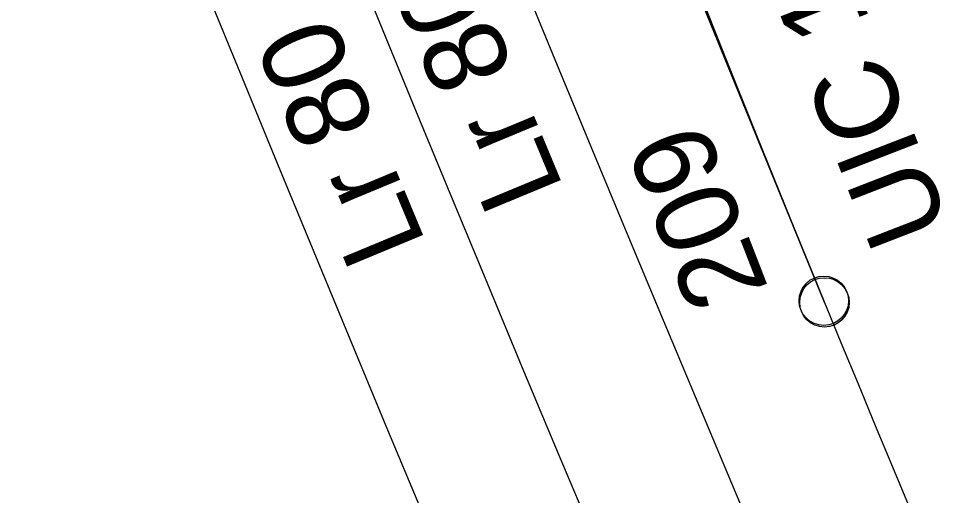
# Model space of a CAD drawing. Extents: x 149855 to 151460, y 6580726 to 6583068.
# Drawn here: x 151020.23 to 151048.78, y 6581433.15 to 6581447.62 of the extents above; entities that cross this region are included whole.
import ezdxf

# ---------------------------------------------------------------- set-up
doc = ezdxf.new("R2010")
doc.units = 0
for name, color, linetype in [('FSK P', 7, 'Continuous'), ('Spårgeometri T', 7, 'Continuous'), ('Spårmitt L', 7, 'Continuous'), ('Tp bef behålls P', 7, 'Continuous'), ('Växel L', 7, 'Continuous'), ('Växelnummer T', 7, 'Continuous'), ('Växeltyp T', 7, 'Continuous')]:
    doc.layers.add(name, color=color, linetype=linetype)

msp = doc.modelspace()

# ---------------------------------------------------------------- linework, layer by layer
at = {"layer": 'FSK P'}
msp.add_circle((151044.69, 6581439.007), 0.75, dxfattribs=at)
at = {"layer": 'Spårmitt L'}
for points in [[(151043.125, 6581430.558), (151042.01, 6581433.189), (151040.901, 6581435.822), (151039.798, 6581438.457), (151038.699, 6581441.095), (151037.606, 6581443.734), (151036.516, 6581446.376), (151035.431, 6581449.019), (151034.35, 6581451.663), (151033.272, 6581454.309), (151032.198, 6581456.957), (151031.126, 6581459.605), (151030.057, 6581462.255), (151028.991, 6581464.906), (151027.926, 6581467.557), (151026.864, 6581470.209), (151025.803, 6581472.862), (151024.743, 6581475.515), (151023.684, 6581478.169), (151022.625, 6581480.823), (151021.567, 6581483.477)], [(151037.777, 6581431.651), (151036.669, 6581434.284), (151035.565, 6581436.92), (151034.467, 6581439.558), (151033.373, 6581442.197), (151032.284, 6581444.838), (151031.199, 6581447.482), (151030.118, 6581450.126), (151029.04, 6581452.772), (151027.966, 6581455.42), (151026.895, 6581458.068), (151025.826, 6581460.718), (151024.759, 6581463.369), (151023.695, 6581466.02), (151022.632, 6581468.672), (151021.571, 6581471.325), (151020.511, 6581473.978), (151019.452, 6581476.632), (151018.394, 6581479.286), (151017.336, 6581481.94)], [(151032.487, 6581432.617), (151031.384, 6581435.253), (151030.286, 6581437.891), (151029.193, 6581440.53), (151028.104, 6581443.172), (151027.019, 6581445.815), (151025.938, 6581448.46), (151024.86, 6581451.106), (151023.786, 6581453.753), (151022.714, 6581456.402), (151021.646, 6581459.052), (151020.579, 6581461.702), (151019.515, 6581464.354), (151018.452, 6581467.006), (151017.391, 6581469.659), (151016.331, 6581472.312), (151015.272, 6581474.966), (151014.214, 6581477.619), (151013.156, 6581480.273)]]:
    msp.add_lwpolyline(points, dxfattribs=at)
for centre, radius, start, end in [((154379.055, 6582805.47), 3603.5, 201.252844, 202.283548), ((151877.457, 6581780.328), 900, 202.283548, 213.397926)]:
    msp.add_arc(centre, radius, start, end, dxfattribs=at)
at = {"layer": 'Tp bef behålls P'}
msp.add_circle((151044.67, 6581439.057), 0.75, dxfattribs=at)
at = {"layer": 'Växel L'}
for p, q in [((151041.178, 6581447.612), (151041.217, 6581447.612)), ((151041.186, 6581447.592), (151041.224, 6581447.592)), ((151041.194, 6581447.572), (151041.232, 6581447.572)), ((151041.202, 6581447.552), (151041.24, 6581447.552)), ((151041.21, 6581447.532), (151041.248, 6581447.532)), ((151041.218, 6581447.512), (151041.256, 6581447.512)), ((151041.226, 6581447.492), (151041.264, 6581447.492)), ((151041.235, 6581447.472), (151041.272, 6581447.472)), ((151041.243, 6581447.452), (151041.28, 6581447.452)), ((151041.251, 6581447.432), (151041.288, 6581447.432)), ((151041.259, 6581447.412), (151041.296, 6581447.412)), ((151041.267, 6581447.392), (151041.304, 6581447.392)), ((151041.275, 6581447.372), (151041.312, 6581447.372)), ((151041.283, 6581447.352), (151041.32, 6581447.352)), ((151041.292, 6581447.332), (151041.328, 6581447.332)), ((151041.3, 6581447.312), (151041.336, 6581447.312)), ((151041.308, 6581447.292), (151041.344, 6581447.292)), ((151041.316, 6581447.272), (151041.352, 6581447.272)), ((151041.324, 6581447.252), (151041.36, 6581447.252)), ((151041.332, 6581447.232), (151041.368, 6581447.232)), ((151041.34, 6581447.212), (151041.376, 6581447.212)), ((151041.349, 6581447.192), (151041.384, 6581447.192)), ((151041.357, 6581447.172), (151041.391, 6581447.172)), ((151041.365, 6581447.152), (151041.399, 6581447.152)), ((151041.373, 6581447.132), (151041.407, 6581447.132)), ((151041.381, 6581447.112), (151041.415, 6581447.112)), ((151041.389, 6581447.092), (151041.423, 6581447.092)), ((151041.397, 6581447.072), (151041.431, 6581447.072)), ((151041.406, 6581447.052), (151041.439, 6581447.052)), ((151041.414, 6581447.032), (151041.447, 6581447.032)), ((151041.422, 6581447.012), (151041.455, 6581447.012)), ((151041.43, 6581446.992), (151041.463, 6581446.992)), ((151041.438, 6581446.972), (151041.471, 6581446.972)), ((151041.446, 6581446.952), (151041.479, 6581446.952)), ((151041.454, 6581446.932), (151041.487, 6581446.932)), ((151041.463, 6581446.912), (151041.495, 6581446.912)), ((151041.471, 6581446.892), (151041.503, 6581446.892)), ((151041.479, 6581446.872), (151041.511, 6581446.872)), ((151041.487, 6581446.852), (151041.519, 6581446.852)), ((151041.495, 6581446.832), (151041.527, 6581446.832)), ((151041.503, 6581446.812), (151041.535, 6581446.812)), ((151041.511, 6581446.792), (151041.543, 6581446.792)), ((151041.52, 6581446.772), (151041.55, 6581446.772)), ((151041.528, 6581446.752), (151041.558, 6581446.752)), ((151041.536, 6581446.732), (151041.566, 6581446.732)), ((151041.544, 6581446.712), (151041.574, 6581446.712)), ((151041.552, 6581446.692), (151041.582, 6581446.692)), ((151041.56, 6581446.672), (151041.59, 6581446.672)), ((151041.568, 6581446.652), (151041.598, 6581446.652)), ((151041.577, 6581446.632), (151041.606, 6581446.632)), ((151041.585, 6581446.612), (151041.614, 6581446.612)), ((151041.593, 6581446.592), (151041.622, 6581446.592)), ((151041.601, 6581446.572), (151041.63, 6581446.572)), ((151041.609, 6581446.552), (151041.638, 6581446.552)), ((151041.617, 6581446.532), (151041.646, 6581446.532)), ((151041.625, 6581446.512), (151041.654, 6581446.512)), ((151041.634, 6581446.492), (151041.662, 6581446.492)), ((151041.642, 6581446.472), (151041.67, 6581446.472)), ((151041.65, 6581446.452), (151041.678, 6581446.452)), ((151041.658, 6581446.432), (151041.686, 6581446.432)), ((151041.666, 6581446.412), (151041.694, 6581446.412)), ((151041.674, 6581446.392), (151041.702, 6581446.392)), ((151041.682, 6581446.372), (151041.71, 6581446.372)), ((151041.691, 6581446.352), (151041.718, 6581446.352)), ((151041.699, 6581446.332), (151041.726, 6581446.332)), ((151041.707, 6581446.312), (151041.734, 6581446.312)), ((151041.715, 6581446.292), (151041.742, 6581446.292)), ((151041.723, 6581446.272), (151041.75, 6581446.272)), ((151041.731, 6581446.252), (151041.758, 6581446.252)), ((151041.739, 6581446.232), (151041.766, 6581446.232)), ((151041.748, 6581446.212), (151041.774, 6581446.212)), ((151041.756, 6581446.192), (151041.782, 6581446.192)), ((151041.764, 6581446.172), (151041.79, 6581446.172)), ((151041.772, 6581446.152), (151041.798, 6581446.152)), ((151041.78, 6581446.132), (151041.806, 6581446.132)), ((151041.788, 6581446.112), (151041.814, 6581446.112)), ((151041.796, 6581446.092), (151041.822, 6581446.092)), ((151041.805, 6581446.072), (151041.83, 6581446.072)), ((151041.813, 6581446.052), (151041.838, 6581446.052)), ((151041.821, 6581446.032), (151041.846, 6581446.032)), ((151041.829, 6581446.012), (151041.854, 6581446.012)), ((151041.837, 6581445.992), (151041.863, 6581445.992)), ((151041.845, 6581445.972), (151041.871, 6581445.972)), ((151041.853, 6581445.952), (151041.879, 6581445.952)), ((151041.862, 6581445.932), (151041.887, 6581445.932)), ((151041.87, 6581445.912), (151041.895, 6581445.912)), ((151041.878, 6581445.892), (151041.903, 6581445.892)), ((151041.886, 6581445.872), (151041.911, 6581445.872)), ((151041.894, 6581445.852), (151041.919, 6581445.852)), ((151041.902, 6581445.832), (151041.927, 6581445.832)), ((151041.91, 6581445.812), (151041.935, 6581445.812)), ((151041.919, 6581445.792), (151041.943, 6581445.792)), ((151041.927, 6581445.772), (151041.951, 6581445.772)), ((151041.935, 6581445.752), (151041.959, 6581445.752)), ((151041.943, 6581445.732), (151041.967, 6581445.732)), ((151041.951, 6581445.712), (151041.975, 6581445.712)), ((151041.959, 6581445.692), (151041.983, 6581445.692)), ((151041.967, 6581445.672), (151041.991, 6581445.672)), ((151041.976, 6581445.652), (151041.999, 6581445.652)), ((151041.984, 6581445.632), (151042.007, 6581445.632)), ((151041.992, 6581445.612), (151042.015, 6581445.612)), ((151042, 6581445.592), (151042.023, 6581445.592)), ((151042.008, 6581445.572), (151042.031, 6581445.572)), ((151042.016, 6581445.552), (151042.039, 6581445.552)), ((151042.024, 6581445.532), (151042.047, 6581445.532)), ((151042.033, 6581445.512), (151042.055, 6581445.512)), ((151042.041, 6581445.492), (151042.063, 6581445.492)), ((151042.049, 6581445.472), (151042.071, 6581445.472)), ((151042.057, 6581445.452), (151042.079, 6581445.452)), ((151042.065, 6581445.432), (151042.087, 6581445.432)), ((151042.073, 6581445.412), (151042.095, 6581445.412)), ((151042.081, 6581445.392), (151042.103, 6581445.392)), ((151042.09, 6581445.372), (151042.111, 6581445.372)), ((151042.098, 6581445.352), (151042.119, 6581445.352)), ((151042.106, 6581445.332), (151042.127, 6581445.332)), ((151042.114, 6581445.312), (151042.135, 6581445.312)), ((151042.122, 6581445.292), (151042.143, 6581445.292)), ((151042.13, 6581445.272), (151042.151, 6581445.272)), ((151042.138, 6581445.252), (151042.159, 6581445.252)), ((151042.147, 6581445.232), (151042.167, 6581445.232)), ((151042.155, 6581445.212), (151042.175, 6581445.212)), ((151042.163, 6581445.192), (151042.183, 6581445.192)), ((151042.171, 6581445.172), (151042.191, 6581445.172)), ((151042.179, 6581445.152), (151042.199, 6581445.152)), ((151042.187, 6581445.132), (151042.207, 6581445.132)), ((151042.195, 6581445.112), (151042.215, 6581445.112)), ((151042.204, 6581445.092), (151042.223, 6581445.092)), ((151042.212, 6581445.072), (151042.231, 6581445.072)), ((151042.22, 6581445.052), (151042.239, 6581445.052)), ((151042.228, 6581445.032), (151042.247, 6581445.032)), ((151042.236, 6581445.012), (151042.256, 6581445.012)), ((151042.244, 6581444.992), (151042.264, 6581444.992)), ((151042.252, 6581444.972), (151042.272, 6581444.972)), ((151042.261, 6581444.952), (151042.28, 6581444.952)), ((151042.269, 6581444.932), (151042.288, 6581444.932)), ((151042.277, 6581444.912), (151042.296, 6581444.912)), ((151042.285, 6581444.892), (151042.304, 6581444.892)), ((151042.293, 6581444.872), (151042.312, 6581444.872)), ((151042.301, 6581444.852), (151042.32, 6581444.852)), ((151042.31, 6581444.832), (151042.328, 6581444.832)), ((151042.318, 6581444.812), (151042.336, 6581444.812)), ((151042.326, 6581444.792), (151042.344, 6581444.792)), ((151042.334, 6581444.772), (151042.352, 6581444.772)), ((151042.342, 6581444.752), (151042.36, 6581444.752)), ((151042.35, 6581444.732), (151042.368, 6581444.732)), ((151042.358, 6581444.712), (151042.376, 6581444.712)), ((151042.367, 6581444.692), (151042.384, 6581444.692)), ((151042.375, 6581444.672), (151042.392, 6581444.672)), ((151042.383, 6581444.652), (151042.4, 6581444.652)), ((151042.391, 6581444.632), (151042.408, 6581444.632)), ((151042.399, 6581444.612), (151042.416, 6581444.612)), ((151042.407, 6581444.592), (151042.424, 6581444.592)), ((151042.415, 6581444.572), (151042.432, 6581444.572)), ((151042.424, 6581444.552), (151042.44, 6581444.552)), ((151042.432, 6581444.532), (151042.448, 6581444.532)), ((151042.44, 6581444.512), (151042.456, 6581444.512)), ((151042.448, 6581444.492), (151042.464, 6581444.492)), ((151042.456, 6581444.472), (151042.472, 6581444.472)), ((151042.464, 6581444.452), (151042.48, 6581444.452)), ((151042.472, 6581444.432), (151042.488, 6581444.432)), ((151042.481, 6581444.412), (151042.496, 6581444.412)), ((151042.489, 6581444.392), (151042.504, 6581444.392)), ((151042.497, 6581444.372), (151042.512, 6581444.372)), ((151042.505, 6581444.352), (151042.52, 6581444.352)), ((151042.513, 6581444.332), (151042.528, 6581444.332)), ((151042.521, 6581444.312), (151042.536, 6581444.312)), ((151042.529, 6581444.292), (151042.544, 6581444.292)), ((151042.538, 6581444.272), (151042.552, 6581444.272)), ((151042.546, 6581444.252), (151042.56, 6581444.252)), ((151042.554, 6581444.232), (151042.568, 6581444.232)), ((151042.562, 6581444.212), (151042.576, 6581444.212)), ((151042.57, 6581444.192), (151042.584, 6581444.192)), ((151042.578, 6581444.172), (151042.592, 6581444.172)), ((151042.586, 6581444.152), (151042.6, 6581444.152)), ((151042.595, 6581444.132), (151042.608, 6581444.132)), ((151042.603, 6581444.112), (151042.616, 6581444.112)), ((151042.611, 6581444.092), (151042.624, 6581444.092)), ((151042.619, 6581444.072), (151042.632, 6581444.072)), ((151042.627, 6581444.052), (151042.64, 6581444.052)), ((151042.635, 6581444.032), (151042.649, 6581444.032)), ((151042.643, 6581444.012), (151042.657, 6581444.012)), ((151042.652, 6581443.992), (151042.665, 6581443.992)), ((151042.66, 6581443.972), (151042.673, 6581443.972)), ((151042.668, 6581443.952), (151042.681, 6581443.952)), ((151042.676, 6581443.932), (151042.689, 6581443.932)), ((151042.684, 6581443.912), (151042.697, 6581443.912)), ((151042.693, 6581443.892), (151042.705, 6581443.892)), ((151042.701, 6581443.872), (151042.713, 6581443.872)), ((151042.709, 6581443.852), (151042.721, 6581443.852)), ((151042.717, 6581443.832), (151042.729, 6581443.832)), ((151042.725, 6581443.812), (151042.738, 6581443.812)), ((151042.733, 6581443.792), (151042.746, 6581443.792)), ((151042.742, 6581443.772), (151042.754, 6581443.772)), ((151042.75, 6581443.752), (151042.762, 6581443.752)), ((151042.758, 6581443.732), (151042.77, 6581443.732)), ((151042.766, 6581443.712), (151042.778, 6581443.712)), ((151042.774, 6581443.692), (151042.786, 6581443.692)), ((151042.782, 6581443.672), (151042.794, 6581443.672)), ((151042.791, 6581443.652), (151042.802, 6581443.652)), ((151042.799, 6581443.632), (151042.81, 6581443.632)), ((151042.807, 6581443.612), (151042.818, 6581443.612)), ((151042.815, 6581443.592), (151042.827, 6581443.592)), ((151042.823, 6581443.572), (151042.835, 6581443.572)), ((151042.832, 6581443.552), (151042.843, 6581443.552)), ((151042.84, 6581443.532), (151042.851, 6581443.532)), ((151042.848, 6581443.512), (151042.859, 6581443.512)), ((151042.856, 6581443.492), (151042.867, 6581443.492)), ((151042.864, 6581443.472), (151042.875, 6581443.472)), ((151042.872, 6581443.452), (151042.883, 6581443.452)), ((151042.881, 6581443.432), (151042.891, 6581443.432)), ((151042.889, 6581443.412), (151042.899, 6581443.412)), ((151042.897, 6581443.392), (151042.907, 6581443.392)), ((151042.905, 6581443.372), (151042.916, 6581443.372)), ((151042.913, 6581443.352), (151042.924, 6581443.352)), ((151042.922, 6581443.332), (151042.932, 6581443.332)), ((151042.93, 6581443.312), (151042.94, 6581443.312)), ((151042.938, 6581443.292), (151042.948, 6581443.292)), ((151042.946, 6581443.272), (151042.956, 6581443.272)), ((151042.954, 6581443.252), (151042.964, 6581443.252)), ((151042.962, 6581443.232), (151042.972, 6581443.232)), ((151042.971, 6581443.212), (151042.98, 6581443.212)), ((151042.979, 6581443.192), (151042.988, 6581443.192)), ((151042.987, 6581443.172), (151042.996, 6581443.172)), ((151042.995, 6581443.152), (151043.005, 6581443.152)), ((151043.003, 6581443.132), (151043.013, 6581443.132)), ((151043.011, 6581443.112), (151043.021, 6581443.112)), ((151043.02, 6581443.092), (151043.029, 6581443.092)), ((151043.028, 6581443.072), (151043.037, 6581443.072)), ((151043.036, 6581443.052), (151043.045, 6581443.052)), ((151043.044, 6581443.032), (151043.053, 6581443.032)), ((151043.052, 6581443.012), (151043.061, 6581443.012)), ((151043.061, 6581442.992), (151043.069, 6581442.992)), ((151043.069, 6581442.972), (151043.077, 6581442.972)), ((151043.077, 6581442.952), (151043.085, 6581442.952)), ((151043.085, 6581442.932), (151043.094, 6581442.932)), ((151043.093, 6581442.912), (151043.102, 6581442.912)), ((151043.101, 6581442.892), (151043.11, 6581442.892)), ((151043.11, 6581442.872), (151043.118, 6581442.872)), ((151043.118, 6581442.852), (151043.126, 6581442.852)), ((151043.126, 6581442.832), (151043.134, 6581442.832)), ((151043.134, 6581442.812), (151043.142, 6581442.812)), ((151043.142, 6581442.792), (151043.15, 6581442.792)), ((151043.151, 6581442.772), (151043.158, 6581442.772)), ((151043.159, 6581442.752), (151043.166, 6581442.752)), ((151043.167, 6581442.732), (151043.174, 6581442.732)), ((151043.175, 6581442.712), (151043.183, 6581442.712)), ((151043.183, 6581442.692), (151043.191, 6581442.692)), ((151043.191, 6581442.672), (151043.199, 6581442.672)), ((151043.2, 6581442.652), (151043.207, 6581442.652)), ((151043.208, 6581442.632), (151043.215, 6581442.632)), ((151043.216, 6581442.612), (151043.223, 6581442.612)), ((151043.224, 6581442.592), (151043.231, 6581442.592)), ((151043.232, 6581442.572), (151043.239, 6581442.572)), ((151043.24, 6581442.552), (151043.247, 6581442.552)), ((151043.249, 6581442.532), (151043.255, 6581442.532)), ((151043.257, 6581442.512), (151043.263, 6581442.512)), ((151043.265, 6581442.492), (151043.271, 6581442.492)), ((151043.273, 6581442.472), (151043.28, 6581442.472)), ((151043.281, 6581442.452), (151043.288, 6581442.452)), ((151043.29, 6581442.432), (151043.296, 6581442.432)), ((151043.298, 6581442.412), (151043.304, 6581442.412)), ((151043.306, 6581442.392), (151043.312, 6581442.392)), ((151043.314, 6581442.372), (151043.32, 6581442.372)), ((151043.322, 6581442.352), (151043.328, 6581442.352)), ((151043.33, 6581442.332), (151043.336, 6581442.332)), ((151043.339, 6581442.312), (151043.344, 6581442.312)), ((151043.347, 6581442.292), (151043.352, 6581442.292)), ((151043.355, 6581442.272), (151043.36, 6581442.272)), ((151043.363, 6581442.252), (151043.369, 6581442.252)), ((151043.371, 6581442.232), (151043.377, 6581442.232)), ((151043.38, 6581442.212), (151043.385, 6581442.212)), ((151043.388, 6581442.192), (151043.393, 6581442.192)), ((151043.396, 6581442.172), (151043.401, 6581442.172)), ((151043.404, 6581442.152), (151043.409, 6581442.152)), ((151043.412, 6581442.132), (151043.417, 6581442.132)), ((151043.42, 6581442.112), (151043.425, 6581442.112)), ((151043.429, 6581442.092), (151043.433, 6581442.092)), ((151043.437, 6581442.072), (151043.441, 6581442.072)), ((151043.445, 6581442.052), (151043.449, 6581442.052)), ((151043.453, 6581442.032), (151043.458, 6581442.032)), ((151043.461, 6581442.012), (151043.466, 6581442.012)), ((151043.469, 6581441.992), (151043.474, 6581441.992)), ((151043.478, 6581441.972), (151043.482, 6581441.972)), ((151043.486, 6581441.952), (151043.49, 6581441.952)), ((151043.494, 6581441.932), (151043.498, 6581441.932)), ((151043.502, 6581441.912), (151043.506, 6581441.912)), ((151043.51, 6581441.892), (151043.514, 6581441.892)), ((151043.519, 6581441.872), (151043.522, 6581441.872)), ((151043.527, 6581441.852), (151043.53, 6581441.852)), ((151043.535, 6581441.832), (151043.538, 6581441.832)), ((151043.543, 6581441.812), (151043.547, 6581441.812)), ((151043.551, 6581441.792), (151043.555, 6581441.792)), ((151043.559, 6581441.772), (151043.563, 6581441.772)), ((151043.568, 6581441.752), (151043.571, 6581441.752)), ((151043.576, 6581441.732), (151043.579, 6581441.732)), ((151043.584, 6581441.712), (151043.587, 6581441.712)), ((151043.592, 6581441.692), (151043.595, 6581441.692)), ((151043.6, 6581441.672), (151043.603, 6581441.672)), ((151043.609, 6581441.652), (151043.611, 6581441.652)), ((151043.617, 6581441.632), (151043.619, 6581441.632)), ((151043.625, 6581441.612), (151043.627, 6581441.612)), ((151043.633, 6581441.592), (151043.636, 6581441.592)), ((151043.641, 6581441.572), (151043.644, 6581441.572)), ((151043.649, 6581441.552), (151043.652, 6581441.552)), ((151043.658, 6581441.532), (151043.66, 6581441.532)), ((151043.666, 6581441.512), (151043.668, 6581441.512)), ((151043.674, 6581441.492), (151043.676, 6581441.492)), ((151043.682, 6581441.472), (151043.684, 6581441.472)), ((151043.69, 6581441.452), (151043.693, 6581441.452)), ((151043.698, 6581441.432), (151043.701, 6581441.432)), ((151043.707, 6581441.412), (151043.709, 6581441.412)), ((151043.715, 6581441.392), (151043.717, 6581441.392)), ((151043.723, 6581441.372), (151043.725, 6581441.372)), ((151043.731, 6581441.352), (151043.733, 6581441.352)), ((151043.739, 6581441.332), (151043.741, 6581441.332)), ((151043.748, 6581441.312), (151043.75, 6581441.312)), ((151043.756, 6581441.292), (151043.758, 6581441.292)), ((151043.764, 6581441.272), (151043.766, 6581441.272)), ((151043.772, 6581441.252), (151043.774, 6581441.252)), ((151043.78, 6581441.232), (151043.782, 6581441.232)), ((151043.788, 6581441.212), (151043.79, 6581441.212)), ((151043.797, 6581441.192), (151043.799, 6581441.192)), ((151043.805, 6581441.172), (151043.807, 6581441.172)), ((151043.813, 6581441.152), (151043.815, 6581441.152)), ((151043.821, 6581441.132), (151043.823, 6581441.132)), ((151043.829, 6581441.112), (151043.831, 6581441.112)), ((151043.838, 6581441.092), (151043.839, 6581441.092)), ((151043.846, 6581441.072), (151043.848, 6581441.072)), ((151043.854, 6581441.052), (151043.856, 6581441.052)), ((151043.862, 6581441.032), (151043.864, 6581441.032)), ((151043.87, 6581441.012), (151043.872, 6581441.012)), ((151043.878, 6581440.992), (151043.88, 6581440.992)), ((151043.887, 6581440.972), (151043.888, 6581440.972)), ((151043.895, 6581440.952), (151043.897, 6581440.952)), ((151043.903, 6581440.932), (151043.905, 6581440.932)), ((151043.911, 6581440.912), (151043.913, 6581440.912)), ((151043.919, 6581440.892), (151043.921, 6581440.892)), ((151043.927, 6581440.872), (151043.929, 6581440.872)), ((151043.936, 6581440.852), (151043.937, 6581440.852)), ((151043.944, 6581440.832), (151043.945, 6581440.832)), ((151043.952, 6581440.812), (151043.954, 6581440.812)), ((151043.96, 6581440.792), (151043.962, 6581440.792)), ((151043.968, 6581440.772), (151043.97, 6581440.772)), ((151043.977, 6581440.752), (151043.978, 6581440.752)), ((151043.985, 6581440.732), (151043.986, 6581440.732)), ((151043.993, 6581440.712), (151043.994, 6581440.712)), ((151044.001, 6581440.692), (151044.003, 6581440.692)), ((151044.009, 6581440.672), (151044.011, 6581440.672)), ((151044.017, 6581440.652), (151044.019, 6581440.652)), ((151044.026, 6581440.632), (151044.027, 6581440.632)), ((151044.034, 6581440.612), (151044.035, 6581440.612)), ((151044.042, 6581440.592), (151044.043, 6581440.592)), ((151044.05, 6581440.572), (151044.052, 6581440.572)), ((151044.058, 6581440.552), (151044.06, 6581440.552)), ((151044.066, 6581440.532), (151044.068, 6581440.532)), ((151044.075, 6581440.512), (151044.076, 6581440.512)), ((151044.083, 6581440.492), (151044.084, 6581440.492)), ((151044.091, 6581440.472), (151044.092, 6581440.472)), ((151044.099, 6581440.452), (151044.101, 6581440.452)), ((151044.107, 6581440.432), (151044.109, 6581440.432)), ((151044.116, 6581440.412), (151044.117, 6581440.412)), ((151044.124, 6581440.392), (151044.125, 6581440.392)), ((151044.132, 6581440.372), (151044.133, 6581440.372)), ((151044.14, 6581440.352), (151044.141, 6581440.352)), ((151044.148, 6581440.332), (151044.149, 6581440.332)), ((151044.156, 6581440.312), (151044.158, 6581440.312)), ((151044.165, 6581440.292), (151044.166, 6581440.292)), ((151044.173, 6581440.272), (151044.174, 6581440.272)), ((151044.181, 6581440.252), (151044.182, 6581440.252)), ((151044.189, 6581440.232), (151044.19, 6581440.232)), ((151044.197, 6581440.212), (151044.198, 6581440.212)), ((151044.206, 6581440.192), (151044.207, 6581440.192)), ((151044.214, 6581440.172), (151044.215, 6581440.172)), ((151044.222, 6581440.152), (151044.223, 6581440.152)), ((151044.23, 6581440.132), (151044.231, 6581440.132)), ((151044.238, 6581440.112), (151044.239, 6581440.112)), ((151044.246, 6581440.092), (151044.247, 6581440.092)), ((151044.255, 6581440.072), (151044.256, 6581440.072)), ((151044.263, 6581440.052), (151044.264, 6581440.052)), ((151044.271, 6581440.032), (151044.272, 6581440.032)), ((151044.279, 6581440.012), (151044.28, 6581440.012)), ((151044.287, 6581439.992), (151044.288, 6581439.992)), ((151044.295, 6581439.972), (151044.296, 6581439.972)), ((151044.304, 6581439.952), (151044.305, 6581439.952)), ((151044.312, 6581439.932), (151044.313, 6581439.932)), ((151044.32, 6581439.912), (151044.321, 6581439.912)), ((151044.328, 6581439.892), (151044.329, 6581439.892)), ((151044.336, 6581439.872), (151044.337, 6581439.872)), ((151044.345, 6581439.852), (151044.345, 6581439.852)), ((151044.353, 6581439.832), (151044.353, 6581439.832)), ((151044.361, 6581439.812), (151044.362, 6581439.812)), ((151044.369, 6581439.792), (151044.37, 6581439.792)), ((151044.377, 6581439.772), (151044.378, 6581439.772)), ((151044.385, 6581439.752), (151044.386, 6581439.752)), ((151044.394, 6581439.732), (151044.394, 6581439.732)), ((151044.402, 6581439.712), (151044.402, 6581439.712)), ((151044.41, 6581439.692), (151044.411, 6581439.692)), ((151044.418, 6581439.672), (151044.419, 6581439.672)), ((151044.426, 6581439.652), (151044.427, 6581439.652)), ((151044.435, 6581439.632), (151044.435, 6581439.632)), ((151044.443, 6581439.612), (151044.443, 6581439.612)), ((151044.451, 6581439.592), (151044.451, 6581439.592)), ((151044.459, 6581439.572), (151044.46, 6581439.572)), ((151044.467, 6581439.552), (151044.468, 6581439.552)), ((151044.475, 6581439.532), (151044.476, 6581439.532)), ((151044.484, 6581439.512), (151044.484, 6581439.512)), ((151044.492, 6581439.492), (151044.492, 6581439.492)), ((151044.5, 6581439.472), (151044.5, 6581439.472)), ((151044.508, 6581439.452), (151044.509, 6581439.452)), ((151044.516, 6581439.432), (151044.517, 6581439.432)), ((151044.524, 6581439.412), (151044.525, 6581439.412)), ((151044.533, 6581439.392), (151044.533, 6581439.392)), ((151044.541, 6581439.372), (151044.541, 6581439.372)), ((151044.549, 6581439.352), (151044.549, 6581439.352)), ((151044.557, 6581439.332), (151044.557, 6581439.332)), ((151044.565, 6581439.312), (151044.566, 6581439.312)), ((151044.574, 6581439.292), (151044.574, 6581439.292)), ((151044.582, 6581439.272), (151044.582, 6581439.272)), ((151044.59, 6581439.252), (151044.59, 6581439.252)), ((151044.598, 6581439.232), (151044.598, 6581439.232)), ((151044.606, 6581439.212), (151044.606, 6581439.212)), ((151044.614, 6581439.192), (151044.615, 6581439.192)), ((151044.623, 6581439.172), (151044.623, 6581439.172)), ((151044.631, 6581439.152), (151044.631, 6581439.152)), ((151044.639, 6581439.132), (151044.639, 6581439.132)), ((151044.647, 6581439.112), (151044.647, 6581439.112)), ((151044.655, 6581439.092), (151044.655, 6581439.092)), ((151044.664, 6581439.072), (151044.664, 6581439.072)), ((151044.672, 6581439.052), (151044.672, 6581439.052)), ((151044.68, 6581439.032), (151044.68, 6581439.032)), ((151044.688, 6581439.012), (151044.688, 6581439.012))]:
    msp.add_line(p, q, dxfattribs=at)
msp.add_lwpolyline([(151034.818, 6581464.166), (151035.769, 6581461.642), (151036.728, 6581459.121), (151037.695, 6581456.603), (151038.668, 6581454.087), (151039.65, 6581451.575), (151040.639, 6581449.065), (151041.635, 6581446.559), (151042.639, 6581444.055), (151043.651, 6581441.554), (151044.67, 6581439.057), (151044.67, 6581439.057), (151044.69, 6581439.007), (151044.67, 6581439.057), (151044.67, 6581439.057), (151042.625, 6581444.057), (151040.588, 6581449.06), (151038.558, 6581454.066), (151036.536, 6581459.076), (151034.522, 6581464.088)], dxfattribs=at)

# ---------------------------------------------------------------- texts
at = {"layer": 'Spårgeometri T'}
for rotation, p in [(112.5714, (151036.789, 6581442.469)), (112.5673, (151032.608, 6581440.802))]:
    msp.add_text('Lr 80', height=2.5, rotation=rotation, dxfattribs=at).set_placement(p)
at = {"layer": 'Växelnummer T'}
msp.add_text('209', height=2.5, rotation=111.1953, dxfattribs=at).set_placement((151043.003, 6581439.42))
at = {"layer": 'Växeltyp T'}
msp.add_text('UIC 1:18.5 IBV', height=2.5, rotation=111.2032, dxfattribs=at).set_placement((151048.517, 6581441.307))

doc.saveas('drawing.dxf')
